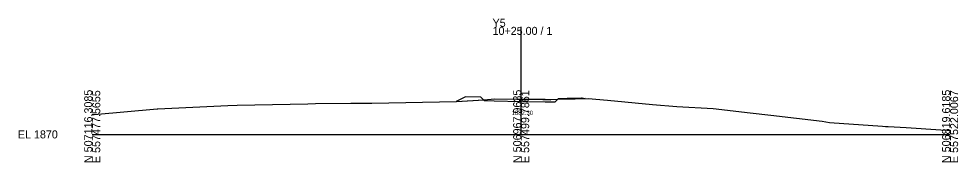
# Model space of a CAD drawing. Extents: x -26 to 1503, y -10 to 2043.
# Drawn here: x 1174.3 to 1502.8, y 490.3 to 540.3 of the extents above; entities that cross this region are included whole.
import ezdxf

# ---------------------------------------------------------------- set-up
doc = ezdxf.new("R2010")
doc.units = 0
for name, color, linetype in [('Exist Cross Section Cell', 7, 'Continuous'), ('Exist XS Ground Line', 7, 'Continuous'), ('Prop XS Ditch Standard Text', 7, 'Continuous'), ('Prop XS Earthwork Shape', 7, 'Continuous')]:
    doc.layers.add(name, color=color, linetype=linetype)

msp = doc.modelspace()

# ---------------------------------------------------------------- linework, layer by layer
at = {"layer": 'Exist Cross Section Cell'}
for p, q in [((1350, 500), (1350, 537.53)), ((1350, 500), (1350, 527.38)), ((1200, 500), (1350, 500)), ((1350, 500), (1500, 500))]:
    msp.add_line(p, q, dxfattribs=at)
at = {"layer": 'Exist XS Ground Line'}
msp.add_lwpolyline([(1200, 506.9), (1200.61, 506.96), (1222.66, 508.94), (1222.99, 508.96), (1227.85, 509.2), (1247.37, 510.11), (1250.67, 510.24), (1275.38, 510.7), (1278.06, 510.79), (1290.46, 510.86), (1295.02, 510.9), (1295.99, 510.88), (1297.76, 510.89), (1327.41, 511.47), (1337.06, 512.11), (1340.66, 512.36), (1348.49, 512.31), (1349.47, 512.31), (1350, 512.3), (1357.57, 512.16), (1358.5, 512.14), (1367.04, 512.39), (1367.73, 512.44), (1368.38, 512.44), (1368.87, 512.46), (1373.42, 512.51), (1380.16, 511.95), (1395.95, 510.43), (1404.42, 509.7), (1417.18, 509.05), (1430.09, 507.49), (1437.32, 506.7), (1455.23, 504.56), (1457.88, 504.17), (1476.39, 502.9), (1477.44, 502.77), (1478.34, 502.71), (1484.62, 502.36), (1496.74, 501.64), (1498.93, 501.5), (1500, 501.45)], dxfattribs=at)
at = {"layer": 'Prop XS Earthwork Shape'}
for points in [[(1336.81, 512.09), (1335.91, 512.99), (1330.5, 513.1), (1327.23, 511.46), (1327.41, 511.47)], [(1362.8, 512.26), (1363.11, 512.58), (1366.05, 512.66), (1371.05, 512.76), (1371.37, 512.72), (1372.35, 512.5), (1368.87, 512.46), (1368.38, 512.44), (1367.73, 512.44), (1367.04, 512.39)], [(1360.43, 512.19), (1362.8, 512.26), (1361.73, 511.19), (1358.43, 511.26), (1350, 511.42), (1340.5, 511.61), (1337.22, 511.68), (1336.81, 512.09), (1337.06, 512.11), (1340.66, 512.36), (1348.49, 512.31), (1349.47, 512.31), (1350, 512.3), (1358.43, 512.13), (1360.43, 512.01)], [(1357.57, 512.16), (1358.43, 512.13), (1350, 512.3)], [(1358.43, 512.13), (1360.43, 512.19), (1360.43, 512.01)]]:
    msp.add_lwpolyline(points, close=True, dxfattribs=at)

# ---------------------------------------------------------------- texts
at = {"layer": 'Exist Cross Section Cell'}
for s, p in [('Y5', (1340, 537.53)), ('10+25.00 / 1', (1340, 534.73)), ('EL 1870', (1174, 498.6))]:
    msp.add_text(s, height=2.8, dxfattribs=at).set_placement(p)
for s, p in [('N 507116.3085', (1200, 490)), ('E 557477.5655', (1202.8, 490)), ('N 506967.9635', (1350, 490)), ('E 557499.7861', (1352.8, 490)), ('N 506819.6185', (1500, 490)), ('E 557522.0067', (1502.8, 490))]:
    msp.add_text(s, height=2.8, rotation=90, dxfattribs=at).set_placement(p)
at = {"layer": 'Prop XS Ditch Standard Text'}
msp.add_text('1882.30', height=1.5, dxfattribs=at).set_placement((1346.66, 506.78))

doc.saveas('drawing.dxf')
